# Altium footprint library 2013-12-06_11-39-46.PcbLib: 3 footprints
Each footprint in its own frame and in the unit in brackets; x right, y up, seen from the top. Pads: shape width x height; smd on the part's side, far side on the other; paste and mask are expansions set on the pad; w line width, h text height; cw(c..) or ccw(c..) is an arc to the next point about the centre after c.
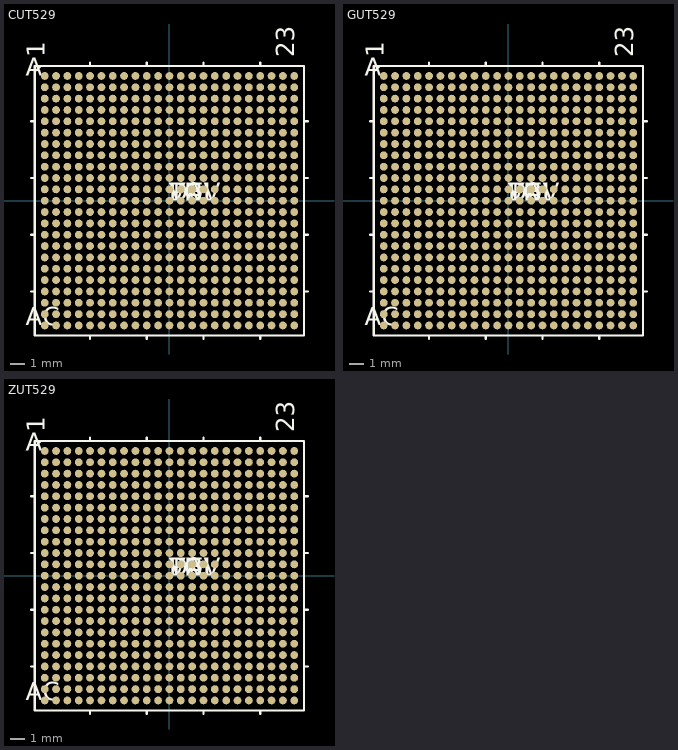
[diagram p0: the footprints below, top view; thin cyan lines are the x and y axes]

## CUT529 [mm]
pads (529):
  round 0.55 smd: A1(-8.8,8.8) A2(-8,8.8) A3(-7.2,8.8) A4(-6.4,8.8) A5(-5.6,8.8) A6(-4.8,8.8) A7(-4,8.8) A8(-3.2,8.8) A9(-2.4,8.8) A10(-1.6,8.8) A11(-0.8,8.8) A12(0,8.8) A13(0.8,8.8) A14(1.6,8.8) A15(2.4,8.8) A16(3.2,8.8) A17(4,8.8) A18(4.8,8.8) A19(5.6,8.8) A20(6.4,8.8) A21(7.2,8.8) A22(8,8.8) A23(8.8,8.8) AA1(-8.8,-7.2) AA2(-8,-7.2) AA3(-7.2,-7.2) AA4(-6.4,-7.2) AA5(-5.6,-7.2) AA6(-4.8,-7.2) AA7(-4,-7.2) AA8(-3.2,-7.2) AA9(-2.4,-7.2) AA10(-1.6,-7.2) AA11(-0.8,-7.2) AA12(0,-7.2) AA13(0.8,-7.2) AA14(1.6,-7.2) AA15(2.4,-7.2) AA16(3.2,-7.2) AA17(4,-7.2) AA18(4.8,-7.2) AA19(5.6,-7.2) AA20(6.4,-7.2) AA21(7.2,-7.2) AA22(8,-7.2) AA23(8.8,-7.2) AB1(-8.8,-8) AB2(-8,-8) AB3(-7.2,-8) AB4(-6.4,-8) AB5(-5.6,-8) AB6(-4.8,-8) AB7(-4,-8) AB8(-3.2,-8) AB9(-2.4,-8) AB10(-1.6,-8) AB11(-0.8,-8) AB12(0,-8) AB13(0.8,-8) AB14(1.6,-8) AB15(2.4,-8) AB16(3.2,-8) AB17(4,-8) AB18(4.8,-8) AB19(5.6,-8) AB20(6.4,-8) AB21(7.2,-8) AB22(8,-8) AB23(8.8,-8) AC1(-8.8,-8.8) AC2(-8,-8.8) AC3(-7.2,-8.8) AC4(-6.4,-8.8) AC5(-5.6,-8.8) AC6(-4.8,-8.8) AC7(-4,-8.8) AC8(-3.2,-8.8) AC9(-2.4,-8.8) AC10(-1.6,-8.8) AC11(-0.8,-8.8) AC12(0,-8.8) AC13(0.8,-8.8) AC14(1.6,-8.8) AC15(2.4,-8.8) AC16(3.2,-8.8) AC17(4,-8.8) AC18(4.8,-8.8) AC19(5.6,-8.8) AC20(6.4,-8.8) AC21(7.2,-8.8) AC22(8,-8.8) AC23(8.8,-8.8) B1(-8.8,8) B2(-8,8) B3(-7.2,8) B4(-6.4,8) B5(-5.6,8) B6(-4.8,8) B7(-4,8) B8(-3.2,8) B9(-2.4,8) B10(-1.6,8) B11(-0.8,8) B12(0,8) B13(0.8,8) B14(1.6,8) B15(2.4,8) B16(3.2,8) B17(4,8) B18(4.8,8) B19(5.6,8) B20(6.4,8) B21(7.2,8) B22(8,8) B23(8.8,8) C1(-8.8,7.2) C2(-8,7.2) C3(-7.2,7.2) C4(-6.4,7.2) C5(-5.6,7.2) C6(-4.8,7.2) C7(-4,7.2) C8(-3.2,7.2) C9(-2.4,7.2) C10(-1.6,7.2) C11(-0.8,7.2) C12(0,7.2) C13(0.8,7.2) C14(1.6,7.2) C15(2.4,7.2) C16(3.2,7.2) C17(4,7.2) C18(4.8,7.2) C19(5.6,7.2) C20(6.4,7.2) C21(7.2,7.2) C22(8,7.2) C23(8.8,7.2) D1(-8.8,6.4) D2(-8,6.4) D3(-7.2,6.4) D4(-6.4,6.4) D5(-5.6,6.4) D6(-4.8,6.4) D7(-4,6.4) D8(-3.2,6.4) D9(-2.4,6.4) D10(-1.6,6.4) D11(-0.8,6.4) D12(0,6.4) D13(0.8,6.4) D14(1.6,6.4) D15(2.4,6.4) D16(3.2,6.4) D17(4,6.4) D18(4.8,6.4) D19(5.6,6.4) D20(6.4,6.4) D21(7.2,6.4) D22(8,6.4) D23(8.8,6.4) E1(-8.8,5.6) E2(-8,5.6) E3(-7.2,5.6) E4(-6.4,5.6) E5(-5.6,5.6) E6(-4.8,5.6) E7(-4,5.6) E8(-3.2,5.6) E9(-2.4,5.6) E10(-1.6,5.6) E11(-0.8,5.6) E12(0,5.6) E13(0.8,5.6) E14(1.6,5.6) E15(2.4,5.6) E16(3.2,5.6) E17(4,5.6) E18(4.8,5.6) E19(5.6,5.6) E20(6.4,5.6) E21(7.2,5.6) E22(8,5.6) E23(8.8,5.6) F1(-8.8,4.8) F2(-8,4.8) F3(-7.2,4.8) F4(-6.4,4.8) F5(-5.6,4.8) F6(-4.8,4.8) F7(-4,4.8) F8(-3.2,4.8) F9(-2.4,4.8) F10(-1.6,4.8) F11(-0.8,4.8) F12(0,4.8) F13(0.8,4.8) F14(1.6,4.8) F15(2.4,4.8) F16(3.2,4.8) F17(4,4.8) F18(4.8,4.8) F19(5.6,4.8) F20(6.4,4.8) F21(7.2,4.8) F22(8,4.8) F23(8.8,4.8) G1(-8.8,4) G2(-8,4) G3(-7.2,4) G4(-6.4,4) G5(-5.6,4) G6(-4.8,4) G7(-4,4) G8(-3.2,4) G9(-2.4,4) G10(-1.6,4) G11(-0.8,4) G12(0,4) G13(0.8,4) G14(1.6,4) G15(2.4,4) G16(3.2,4) G17(4,4) G18(4.8,4) G19(5.6,4) G20(6.4,4) G21(7.2,4) G22(8,4) G23(8.8,4) H1(-8.8,3.2) H2(-8,3.2) H3(-7.2,3.2) H4(-6.4,3.2) H5(-5.6,3.2) H6(-4.8,3.2) H7(-4,3.2) H8(-3.2,3.2) H9(-2.4,3.2) H10(-1.6,3.2) H11(-0.8,3.2) H12(0,3.2) H13(0.8,3.2) H14(1.6,3.2) H15(2.4,3.2) H16(3.2,3.2) H17(4,3.2) H18(4.8,3.2) H19(5.6,3.2) H20(6.4,3.2) H21(7.2,3.2) H22(8,3.2) H23(8.8,3.2) J1(-8.8,2.4) J2(-8,2.4) J3(-7.2,2.4) J4(-6.4,2.4) J5(-5.6,2.4) J6(-4.8,2.4) J7(-4,2.4) J8(-3.2,2.4) J9(-2.4,2.4) J10(-1.6,2.4) J11(-0.8,2.4) J12(0,2.4) J13(0.8,2.4) J14(1.6,2.4) J15(2.4,2.4) J16(3.2,2.4) J17(4,2.4) J18(4.8,2.4) J19(5.6,2.4) J20(6.4,2.4) J21(7.2,2.4) J22(8,2.4) J23(8.8,2.4) K1(-8.8,1.6) K2(-8,1.6) K3(-7.2,1.6) K4(-6.4,1.6) K5(-5.6,1.6) K6(-4.8,1.6) K7(-4,1.6) K8(-3.2,1.6) K9(-2.4,1.6) K10(-1.6,1.6) K11(-0.8,1.6) K12(0,1.6) K13(0.8,1.6) K14(1.6,1.6) K15(2.4,1.6) K16(3.2,1.6) K17(4,1.6) K18(4.8,1.6) K19(5.6,1.6) K20(6.4,1.6) K21(7.2,1.6) K22(8,1.6) K23(8.8,1.6) L1(-8.8,0.8) L2(-8,0.8) L3(-7.2,0.8) L4(-6.4,0.8) L5(-5.6,0.8) L6(-4.8,0.8) L7(-4,0.8) L8(-3.2,0.8) L9(-2.4,0.8) L10(-1.6,0.8) L11(-0.8,0.8) L12(0,0.8) L13(0.8,0.8) L14(1.6,0.8) L15(2.4,0.8) L16(3.2,0.8) L17(4,0.8) L18(4.8,0.8) L19(5.6,0.8) L20(6.4,0.8) L21(7.2,0.8) L22(8,0.8) L23(8.8,0.8) M1(-8.8,0) M2(-8,0) M3(-7.2,0) M4(-6.4,0) M5(-5.6,0) M6(-4.8,0) M7(-4,0) M8(-3.2,0) M9(-2.4,0) M10(-1.6,0) M11(-0.8,0) M12(0,0) M13(0.8,0) M14(1.6,0) M15(2.4,0) M16(3.2,0) M17(4,0) M18(4.8,0) M19(5.6,0) M20(6.4,0) M21(7.2,0) M22(8,0) M23(8.8,0) N1(-8.8,-0.8) N2(-8,-0.8) N3(-7.2,-0.8) N4(-6.4,-0.8) N5(-5.6,-0.8) N6(-4.8,-0.8) N7(-4,-0.8) N8(-3.2,-0.8) N9(-2.4,-0.8) N10(-1.6,-0.8) N11(-0.8,-0.8) N12(0,-0.8) N13(0.8,-0.8) N14(1.6,-0.8) N15(2.4,-0.8) N16(3.2,-0.8) N17(4,-0.8) N18(4.8,-0.8) N19(5.6,-0.8) N20(6.4,-0.8) N21(7.2,-0.8) N22(8,-0.8) N23(8.8,-0.8) P1(-8.8,-1.6) P2(-8,-1.6) P3(-7.2,-1.6) P4(-6.4,-1.6) P5(-5.6,-1.6) P6(-4.8,-1.6) P7(-4,-1.6) P8(-3.2,-1.6) P9(-2.4,-1.6) P10(-1.6,-1.6) P11(-0.8,-1.6) P12(0,-1.6) P13(0.8,-1.6) P14(1.6,-1.6) P15(2.4,-1.6) P16(3.2,-1.6) P17(4,-1.6) P18(4.8,-1.6) P19(5.6,-1.6) P20(6.4,-1.6) P21(7.2,-1.6) P22(8,-1.6) P23(8.8,-1.6) R1(-8.8,-2.4) R2(-8,-2.4) R3(-7.2,-2.4) R4(-6.4,-2.4) R5(-5.6,-2.4) R6(-4.8,-2.4) R7(-4,-2.4) R8(-3.2,-2.4) R9(-2.4,-2.4) R10(-1.6,-2.4) R11(-0.8,-2.4) R12(0,-2.4) R13(0.8,-2.4) R14(1.6,-2.4) R15(2.4,-2.4) R16(3.2,-2.4) R17(4,-2.4) R18(4.8,-2.4) R19(5.6,-2.4) R20(6.4,-2.4) R21(7.2,-2.4) R22(8,-2.4) R23(8.8,-2.4) T1(-8.8,-3.2) T2(-8,-3.2) T3(-7.2,-3.2) T4(-6.4,-3.2) T5(-5.6,-3.2) T6(-4.8,-3.2) T7(-4,-3.2) T8(-3.2,-3.2) T9(-2.4,-3.2) T10(-1.6,-3.2) T11(-0.8,-3.2) T12(0,-3.2) T13(0.8,-3.2) T14(1.6,-3.2) T15(2.4,-3.2) T16(3.2,-3.2) T17(4,-3.2) T18(4.8,-3.2) T19(5.6,-3.2) T20(6.4,-3.2) T21(7.2,-3.2) T22(8,-3.2) T23(8.8,-3.2) U1(-8.8,-4) U2(-8,-4) U3(-7.2,-4) U4(-6.4,-4) U5(-5.6,-4) U6(-4.8,-4) U7(-4,-4) U8(-3.2,-4) U9(-2.4,-4) U10(-1.6,-4) U11(-0.8,-4) U12(0,-4) U13(0.8,-4) U14(1.6,-4) U15(2.4,-4) U16(3.2,-4) U17(4,-4) U18(4.8,-4) U19(5.6,-4) U20(6.4,-4) U21(7.2,-4) U22(8,-4) U23(8.8,-4) V1(-8.8,-4.8) V2(-8,-4.8) V3(-7.2,-4.8) V4(-6.4,-4.8) V5(-5.6,-4.8) V6(-4.8,-4.8) V7(-4,-4.8) V8(-3.2,-4.8) V9(-2.4,-4.8) V10(-1.6,-4.8) V11(-0.8,-4.8) V12(0,-4.8) V13(0.8,-4.8) V14(1.6,-4.8) V15(2.4,-4.8) V16(3.2,-4.8) V17(4,-4.8) V18(4.8,-4.8) V19(5.6,-4.8) V20(6.4,-4.8) V21(7.2,-4.8) V22(8,-4.8) V23(8.8,-4.8) W1(-8.8,-5.6) W2(-8,-5.6) W3(-7.2,-5.6) W4(-6.4,-5.6) W5(-5.6,-5.6) W6(-4.8,-5.6) W7(-4,-5.6) W8(-3.2,-5.6) W9(-2.4,-5.6) W10(-1.6,-5.6) W11(-0.8,-5.6) W12(0,-5.6) W13(0.8,-5.6) W14(1.6,-5.6) W15(2.4,-5.6) W16(3.2,-5.6) W17(4,-5.6) W18(4.8,-5.6) W19(5.6,-5.6) W20(6.4,-5.6) W21(7.2,-5.6) W22(8,-5.6) W23(8.8,-5.6) Y1(-8.8,-6.4) Y2(-8,-6.4) Y3(-7.2,-6.4) Y4(-6.4,-6.4) Y5(-5.6,-6.4) Y6(-4.8,-6.4) Y7(-4,-6.4) Y8(-3.2,-6.4) Y9(-2.4,-6.4) Y10(-1.6,-6.4) Y11(-0.8,-6.4) Y12(0,-6.4) Y13(0.8,-6.4) Y14(1.6,-6.4) Y15(2.4,-6.4) Y16(3.2,-6.4) Y17(4,-6.4) Y18(4.8,-6.4) Y19(5.6,-6.4) Y20(6.4,-6.4) Y21(7.2,-6.4) Y22(8,-6.4) Y23(8.8,-6.4)
Top Overlay:
  lines w0.152: -9.754,-6.4 -9.5,-6.4 ; -9.754,-2.4 -9.5,-2.4 ; -9.754,1.6 -9.5,1.6 ; -9.754,5.6 -9.5,5.6 ; -9.5,9.1 -9.1,9.5 ; -5.6,-9.754 -5.6,-9.5 ; -5.6,9.5 -5.6,9.754 ; -1.6,-9.754 -1.6,-9.5 ; -1.6,9.5 -1.6,9.754 ; 2.4,-9.754 2.4,-9.5 ; 2.4,9.5 2.4,9.754 ; 6.4,-9.754 6.4,-9.5 ; 6.4,9.5 6.4,9.754 ; 9.5,-6.4 9.754,-6.4 ; 9.5,-2.4 9.754,-2.4 ; 9.5,1.6 9.754,1.6 ; 9.5,5.6 9.754,5.6 ; -9.5,-9.5 9.5,-9.5 9.5,9.5 -9.5,9.5 -9.5,-9.5
  text "A" at -10.135,8.8 h1.27
  text "AC" at -10.135,-8.8 h1.27
  text "1" at -8.8,10.135 h1.27
  text "23" at 8.8,10.135 h1.27
  text "PN" at 0,0 h1.27
  text "DEV" at 0,0 h1.27
  text "VAL" at 0,0 h1.27
  text "TOL" at 0,0 h1.27
Bottom Overlay:
  text "A" at -10.135,8.8 h1.27
  text "AC" at -10.135,-8.8 h1.27
  text "1" at -8.8,10.135 h1.27
  text "23" at 8.8,10.135 h1.27
Mechanical 1:
  lines w0: -9.5,9.1 -9.1,9.5 ; -9.5,-9.5 9.5,-9.5 9.5,9.5 -9.5,9.5 -9.5,-9.5
  text "A" at -10.135,8.8 h1.27
  text "AC" at -10.135,-8.8 h1.27
  text "1" at -8.8,10.135 h1.27
  text "23" at 8.8,10.135 h1.27
  text "RefDes2" at 0,0 h1.27

## GUT529 [mm]
pads (529):
  round 0.55 smd: A1(-8.8,8.8) A2(-8,8.8) A3(-7.2,8.8) A4(-6.4,8.8) A5(-5.6,8.8) A6(-4.8,8.8) A7(-4,8.8) A8(-3.2,8.8) A9(-2.4,8.8) A10(-1.6,8.8) A11(-0.8,8.8) A12(0,8.8) A13(0.8,8.8) A14(1.6,8.8) A15(2.4,8.8) A16(3.2,8.8) A17(4,8.8) A18(4.8,8.8) A19(5.6,8.8) A20(6.4,8.8) A21(7.2,8.8) A22(8,8.8) A23(8.8,8.8) AA1(-8.8,-7.2) AA2(-8,-7.2) AA3(-7.2,-7.2) AA4(-6.4,-7.2) AA5(-5.6,-7.2) AA6(-4.8,-7.2) AA7(-4,-7.2) AA8(-3.2,-7.2) AA9(-2.4,-7.2) AA10(-1.6,-7.2) AA11(-0.8,-7.2) AA12(0,-7.2) AA13(0.8,-7.2) AA14(1.6,-7.2) AA15(2.4,-7.2) AA16(3.2,-7.2) AA17(4,-7.2) AA18(4.8,-7.2) AA19(5.6,-7.2) AA20(6.4,-7.2) AA21(7.2,-7.2) AA22(8,-7.2) AA23(8.8,-7.2) AB1(-8.8,-8) AB2(-8,-8) AB3(-7.2,-8) AB4(-6.4,-8) AB5(-5.6,-8) AB6(-4.8,-8) AB7(-4,-8) AB8(-3.2,-8) AB9(-2.4,-8) AB10(-1.6,-8) AB11(-0.8,-8) AB12(0,-8) AB13(0.8,-8) AB14(1.6,-8) AB15(2.4,-8) AB16(3.2,-8) AB17(4,-8) AB18(4.8,-8) AB19(5.6,-8) AB20(6.4,-8) AB21(7.2,-8) AB22(8,-8) AB23(8.8,-8) AC1(-8.8,-8.8) AC2(-8,-8.8) AC3(-7.2,-8.8) AC4(-6.4,-8.8) AC5(-5.6,-8.8) AC6(-4.8,-8.8) AC7(-4,-8.8) AC8(-3.2,-8.8) AC9(-2.4,-8.8) AC10(-1.6,-8.8) AC11(-0.8,-8.8) AC12(0,-8.8) AC13(0.8,-8.8) AC14(1.6,-8.8) AC15(2.4,-8.8) AC16(3.2,-8.8) AC17(4,-8.8) AC18(4.8,-8.8) AC19(5.6,-8.8) AC20(6.4,-8.8) AC21(7.2,-8.8) AC22(8,-8.8) AC23(8.8,-8.8) B1(-8.8,8) B2(-8,8) B3(-7.2,8) B4(-6.4,8) B5(-5.6,8) B6(-4.8,8) B7(-4,8) B8(-3.2,8) B9(-2.4,8) B10(-1.6,8) B11(-0.8,8) B12(0,8) B13(0.8,8) B14(1.6,8) B15(2.4,8) B16(3.2,8) B17(4,8) B18(4.8,8) B19(5.6,8) B20(6.4,8) B21(7.2,8) B22(8,8) B23(8.8,8) C1(-8.8,7.2) C2(-8,7.2) C3(-7.2,7.2) C4(-6.4,7.2) C5(-5.6,7.2) C6(-4.8,7.2) C7(-4,7.2) C8(-3.2,7.2) C9(-2.4,7.2) C10(-1.6,7.2) C11(-0.8,7.2) C12(0,7.2) C13(0.8,7.2) C14(1.6,7.2) C15(2.4,7.2) C16(3.2,7.2) C17(4,7.2) C18(4.8,7.2) C19(5.6,7.2) C20(6.4,7.2) C21(7.2,7.2) C22(8,7.2) C23(8.8,7.2) D1(-8.8,6.4) D2(-8,6.4) D3(-7.2,6.4) D4(-6.4,6.4) D5(-5.6,6.4) D6(-4.8,6.4) D7(-4,6.4) D8(-3.2,6.4) D9(-2.4,6.4) D10(-1.6,6.4) D11(-0.8,6.4) D12(0,6.4) D13(0.8,6.4) D14(1.6,6.4) D15(2.4,6.4) D16(3.2,6.4) D17(4,6.4) D18(4.8,6.4) D19(5.6,6.4) D20(6.4,6.4) D21(7.2,6.4) D22(8,6.4) D23(8.8,6.4) E1(-8.8,5.6) E2(-8,5.6) E3(-7.2,5.6) E4(-6.4,5.6) E5(-5.6,5.6) E6(-4.8,5.6) E7(-4,5.6) E8(-3.2,5.6) E9(-2.4,5.6) E10(-1.6,5.6) E11(-0.8,5.6) E12(0,5.6) E13(0.8,5.6) E14(1.6,5.6) E15(2.4,5.6) E16(3.2,5.6) E17(4,5.6) E18(4.8,5.6) E19(5.6,5.6) E20(6.4,5.6) E21(7.2,5.6) E22(8,5.6) E23(8.8,5.6) F1(-8.8,4.8) F2(-8,4.8) F3(-7.2,4.8) F4(-6.4,4.8) F5(-5.6,4.8) F6(-4.8,4.8) F7(-4,4.8) F8(-3.2,4.8) F9(-2.4,4.8) F10(-1.6,4.8) F11(-0.8,4.8) F12(0,4.8) F13(0.8,4.8) F14(1.6,4.8) F15(2.4,4.8) F16(3.2,4.8) F17(4,4.8) F18(4.8,4.8) F19(5.6,4.8) F20(6.4,4.8) F21(7.2,4.8) F22(8,4.8) F23(8.8,4.8) G1(-8.8,4) G2(-8,4) G3(-7.2,4) G4(-6.4,4) G5(-5.6,4) G6(-4.8,4) G7(-4,4) G8(-3.2,4) G9(-2.4,4) G10(-1.6,4) G11(-0.8,4) G12(0,4) G13(0.8,4) G14(1.6,4) G15(2.4,4) G16(3.2,4) G17(4,4) G18(4.8,4) G19(5.6,4) G20(6.4,4) G21(7.2,4) G22(8,4) G23(8.8,4) H1(-8.8,3.2) H2(-8,3.2) H3(-7.2,3.2) H4(-6.4,3.2) H5(-5.6,3.2) H6(-4.8,3.2) H7(-4,3.2) H8(-3.2,3.2) H9(-2.4,3.2) H10(-1.6,3.2) H11(-0.8,3.2) H12(0,3.2) H13(0.8,3.2) H14(1.6,3.2) H15(2.4,3.2) H16(3.2,3.2) H17(4,3.2) H18(4.8,3.2) H19(5.6,3.2) H20(6.4,3.2) H21(7.2,3.2) H22(8,3.2) H23(8.8,3.2) J1(-8.8,2.4) J2(-8,2.4) J3(-7.2,2.4) J4(-6.4,2.4) J5(-5.6,2.4) J6(-4.8,2.4) J7(-4,2.4) J8(-3.2,2.4) J9(-2.4,2.4) J10(-1.6,2.4) J11(-0.8,2.4) J12(0,2.4) J13(0.8,2.4) J14(1.6,2.4) J15(2.4,2.4) J16(3.2,2.4) J17(4,2.4) J18(4.8,2.4) J19(5.6,2.4) J20(6.4,2.4) J21(7.2,2.4) J22(8,2.4) J23(8.8,2.4) K1(-8.8,1.6) K2(-8,1.6) K3(-7.2,1.6) K4(-6.4,1.6) K5(-5.6,1.6) K6(-4.8,1.6) K7(-4,1.6) K8(-3.2,1.6) K9(-2.4,1.6) K10(-1.6,1.6) K11(-0.8,1.6) K12(0,1.6) K13(0.8,1.6) K14(1.6,1.6) K15(2.4,1.6) K16(3.2,1.6) K17(4,1.6) K18(4.8,1.6) K19(5.6,1.6) K20(6.4,1.6) K21(7.2,1.6) K22(8,1.6) K23(8.8,1.6) L1(-8.8,0.8) L2(-8,0.8) L3(-7.2,0.8) L4(-6.4,0.8) L5(-5.6,0.8) L6(-4.8,0.8) L7(-4,0.8) L8(-3.2,0.8) L9(-2.4,0.8) L10(-1.6,0.8) L11(-0.8,0.8) L12(0,0.8) L13(0.8,0.8) L14(1.6,0.8) L15(2.4,0.8) L16(3.2,0.8) L17(4,0.8) L18(4.8,0.8) L19(5.6,0.8) L20(6.4,0.8) L21(7.2,0.8) L22(8,0.8) L23(8.8,0.8) M1(-8.8,0) M2(-8,0) M3(-7.2,0) M4(-6.4,0) M5(-5.6,0) M6(-4.8,0) M7(-4,0) M8(-3.2,0) M9(-2.4,0) M10(-1.6,0) M11(-0.8,0) M12(0,0) M13(0.8,0) M14(1.6,0) M15(2.4,0) M16(3.2,0) M17(4,0) M18(4.8,0) M19(5.6,0) M20(6.4,0) M21(7.2,0) M22(8,0) M23(8.8,0) N1(-8.8,-0.8) N2(-8,-0.8) N3(-7.2,-0.8) N4(-6.4,-0.8) N5(-5.6,-0.8) N6(-4.8,-0.8) N7(-4,-0.8) N8(-3.2,-0.8) N9(-2.4,-0.8) N10(-1.6,-0.8) N11(-0.8,-0.8) N12(0,-0.8) N13(0.8,-0.8) N14(1.6,-0.8) N15(2.4,-0.8) N16(3.2,-0.8) N17(4,-0.8) N18(4.8,-0.8) N19(5.6,-0.8) N20(6.4,-0.8) N21(7.2,-0.8) N22(8,-0.8) N23(8.8,-0.8) P1(-8.8,-1.6) P2(-8,-1.6) P3(-7.2,-1.6) P4(-6.4,-1.6) P5(-5.6,-1.6) P6(-4.8,-1.6) P7(-4,-1.6) P8(-3.2,-1.6) P9(-2.4,-1.6) P10(-1.6,-1.6) P11(-0.8,-1.6) P12(0,-1.6) P13(0.8,-1.6) P14(1.6,-1.6) P15(2.4,-1.6) P16(3.2,-1.6) P17(4,-1.6) P18(4.8,-1.6) P19(5.6,-1.6) P20(6.4,-1.6) P21(7.2,-1.6) P22(8,-1.6) P23(8.8,-1.6) R1(-8.8,-2.4) R2(-8,-2.4) R3(-7.2,-2.4) R4(-6.4,-2.4) R5(-5.6,-2.4) R6(-4.8,-2.4) R7(-4,-2.4) R8(-3.2,-2.4) R9(-2.4,-2.4) R10(-1.6,-2.4) R11(-0.8,-2.4) R12(0,-2.4) R13(0.8,-2.4) R14(1.6,-2.4) R15(2.4,-2.4) R16(3.2,-2.4) R17(4,-2.4) R18(4.8,-2.4) R19(5.6,-2.4) R20(6.4,-2.4) R21(7.2,-2.4) R22(8,-2.4) R23(8.8,-2.4) T1(-8.8,-3.2) T2(-8,-3.2) T3(-7.2,-3.2) T4(-6.4,-3.2) T5(-5.6,-3.2) T6(-4.8,-3.2) T7(-4,-3.2) T8(-3.2,-3.2) T9(-2.4,-3.2) T10(-1.6,-3.2) T11(-0.8,-3.2) T12(0,-3.2) T13(0.8,-3.2) T14(1.6,-3.2) T15(2.4,-3.2) T16(3.2,-3.2) T17(4,-3.2) T18(4.8,-3.2) T19(5.6,-3.2) T20(6.4,-3.2) T21(7.2,-3.2) T22(8,-3.2) T23(8.8,-3.2) U1(-8.8,-4) U2(-8,-4) U3(-7.2,-4) U4(-6.4,-4) U5(-5.6,-4) U6(-4.8,-4) U7(-4,-4) U8(-3.2,-4) U9(-2.4,-4) U10(-1.6,-4) U11(-0.8,-4) U12(0,-4) U13(0.8,-4) U14(1.6,-4) U15(2.4,-4) U16(3.2,-4) U17(4,-4) U18(4.8,-4) U19(5.6,-4) U20(6.4,-4) U21(7.2,-4) U22(8,-4) U23(8.8,-4) V1(-8.8,-4.8) V2(-8,-4.8) V3(-7.2,-4.8) V4(-6.4,-4.8) V5(-5.6,-4.8) V6(-4.8,-4.8) V7(-4,-4.8) V8(-3.2,-4.8) V9(-2.4,-4.8) V10(-1.6,-4.8) V11(-0.8,-4.8) V12(0,-4.8) V13(0.8,-4.8) V14(1.6,-4.8) V15(2.4,-4.8) V16(3.2,-4.8) V17(4,-4.8) V18(4.8,-4.8) V19(5.6,-4.8) V20(6.4,-4.8) V21(7.2,-4.8) V22(8,-4.8) V23(8.8,-4.8) W1(-8.8,-5.6) W2(-8,-5.6) W3(-7.2,-5.6) W4(-6.4,-5.6) W5(-5.6,-5.6) W6(-4.8,-5.6) W7(-4,-5.6) W8(-3.2,-5.6) W9(-2.4,-5.6) W10(-1.6,-5.6) W11(-0.8,-5.6) W12(0,-5.6) W13(0.8,-5.6) W14(1.6,-5.6) W15(2.4,-5.6) W16(3.2,-5.6) W17(4,-5.6) W18(4.8,-5.6) W19(5.6,-5.6) W20(6.4,-5.6) W21(7.2,-5.6) W22(8,-5.6) W23(8.8,-5.6) Y1(-8.8,-6.4) Y2(-8,-6.4) Y3(-7.2,-6.4) Y4(-6.4,-6.4) Y5(-5.6,-6.4) Y6(-4.8,-6.4) Y7(-4,-6.4) Y8(-3.2,-6.4) Y9(-2.4,-6.4) Y10(-1.6,-6.4) Y11(-0.8,-6.4) Y12(0,-6.4) Y13(0.8,-6.4) Y14(1.6,-6.4) Y15(2.4,-6.4) Y16(3.2,-6.4) Y17(4,-6.4) Y18(4.8,-6.4) Y19(5.6,-6.4) Y20(6.4,-6.4) Y21(7.2,-6.4) Y22(8,-6.4) Y23(8.8,-6.4)
Top Overlay:
  lines w0.152: -9.754,-6.4 -9.5,-6.4 ; -9.754,-2.4 -9.5,-2.4 ; -9.754,1.6 -9.5,1.6 ; -9.754,5.6 -9.5,5.6 ; -9.5,9.1 -9.1,9.5 ; -5.6,-9.754 -5.6,-9.5 ; -5.6,9.5 -5.6,9.754 ; -1.6,-9.754 -1.6,-9.5 ; -1.6,9.5 -1.6,9.754 ; 2.4,-9.754 2.4,-9.5 ; 2.4,9.5 2.4,9.754 ; 6.4,-9.754 6.4,-9.5 ; 6.4,9.5 6.4,9.754 ; 9.5,-6.4 9.754,-6.4 ; 9.5,-2.4 9.754,-2.4 ; 9.5,1.6 9.754,1.6 ; 9.5,5.6 9.754,5.6 ; -9.5,-9.5 9.5,-9.5 9.5,9.5 -9.5,9.5 -9.5,-9.5
  text "A" at -10.135,8.8 h1.27
  text "AC" at -10.135,-8.8 h1.27
  text "1" at -8.8,10.135 h1.27
  text "23" at 8.8,10.135 h1.27
  text "PN" at 0,0 h1.27
  text "DEV" at 0,0 h1.27
  text "VAL" at 0,0 h1.27
  text "TOL" at 0,0 h1.27
Bottom Overlay:
  text "A" at -10.135,8.8 h1.27
  text "AC" at -10.135,-8.8 h1.27
  text "1" at -8.8,10.135 h1.27
  text "23" at 8.8,10.135 h1.27
Mechanical 1:
  lines w0: -9.5,9.1 -9.1,9.5 ; -9.5,-9.5 9.5,-9.5 9.5,9.5 -9.5,9.5 -9.5,-9.5
  text "A" at -10.135,8.8 h1.27
  text "AC" at -10.135,-8.8 h1.27
  text "1" at -8.8,10.135 h1.27
  text "23" at 8.8,10.135 h1.27
  text "RefDes2" at 0,0 h1.27

## ZUT529 [mm]
pads (529):
  round 0.55 smd: A1(-8.8,8.8) A2(-8,8.8) A3(-7.2,8.8) A4(-6.4,8.8) A5(-5.6,8.8) A6(-4.8,8.8) A7(-4,8.8) A8(-3.2,8.8) A9(-2.4,8.8) A10(-1.6,8.8) A11(-0.8,8.8) A12(0,8.8) A13(0.8,8.8) A14(1.6,8.8) A15(2.4,8.8) A16(3.2,8.8) A17(4,8.8) A18(4.8,8.8) A19(5.6,8.8) A20(6.4,8.8) A21(7.2,8.8) A22(8,8.8) A23(8.8,8.8) AA1(-8.8,-7.2) AA2(-8,-7.2) AA3(-7.2,-7.2) AA4(-6.4,-7.2) AA5(-5.6,-7.2) AA6(-4.8,-7.2) AA7(-4,-7.2) AA8(-3.2,-7.2) AA9(-2.4,-7.2) AA10(-1.6,-7.2) AA11(-0.8,-7.2) AA12(0,-7.2) AA13(0.8,-7.2) AA14(1.6,-7.2) AA15(2.4,-7.2) AA16(3.2,-7.2) AA17(4,-7.2) AA18(4.8,-7.2) AA19(5.6,-7.2) AA20(6.4,-7.2) AA21(7.2,-7.2) AA22(8,-7.2) AA23(8.8,-7.2) AB1(-8.8,-8) AB2(-8,-8) AB3(-7.2,-8) AB4(-6.4,-8) AB5(-5.6,-8) AB6(-4.8,-8) AB7(-4,-8) AB8(-3.2,-8) AB9(-2.4,-8) AB10(-1.6,-8) AB11(-0.8,-8) AB12(0,-8) AB13(0.8,-8) AB14(1.6,-8) AB15(2.4,-8) AB16(3.2,-8) AB17(4,-8) AB18(4.8,-8) AB19(5.6,-8) AB20(6.4,-8) AB21(7.2,-8) AB22(8,-8) AB23(8.8,-8) AC1(-8.8,-8.8) AC2(-8,-8.8) AC3(-7.2,-8.8) AC4(-6.4,-8.8) AC5(-5.6,-8.8) AC6(-4.8,-8.8) AC7(-4,-8.8) AC8(-3.2,-8.8) AC9(-2.4,-8.8) AC10(-1.6,-8.8) AC11(-0.8,-8.8) AC12(0,-8.8) AC13(0.8,-8.8) AC14(1.6,-8.8) AC15(2.4,-8.8) AC16(3.2,-8.8) AC17(4,-8.8) AC18(4.8,-8.8) AC19(5.6,-8.8) AC20(6.4,-8.8) AC21(7.2,-8.8) AC22(8,-8.8) AC23(8.8,-8.8) B1(-8.8,8) B2(-8,8) B3(-7.2,8) B4(-6.4,8) B5(-5.6,8) B6(-4.8,8) B7(-4,8) B8(-3.2,8) B9(-2.4,8) B10(-1.6,8) B11(-0.8,8) B12(0,8) B13(0.8,8) B14(1.6,8) B15(2.4,8) B16(3.2,8) B17(4,8) B18(4.8,8) B19(5.6,8) B20(6.4,8) B21(7.2,8) B22(8,8) B23(8.8,8) C1(-8.8,7.2) C2(-8,7.2) C3(-7.2,7.2) C4(-6.4,7.2) C5(-5.6,7.2) C6(-4.8,7.2) C7(-4,7.2) C8(-3.2,7.2) C9(-2.4,7.2) C10(-1.6,7.2) C11(-0.8,7.2) C12(0,7.2) C13(0.8,7.2) C14(1.6,7.2) C15(2.4,7.2) C16(3.2,7.2) C17(4,7.2) C18(4.8,7.2) C19(5.6,7.2) C20(6.4,7.2) C21(7.2,7.2) C22(8,7.2) C23(8.8,7.2) D1(-8.8,6.4) D2(-8,6.4) D3(-7.2,6.4) D4(-6.4,6.4) D5(-5.6,6.4) D6(-4.8,6.4) D7(-4,6.4) D8(-3.2,6.4) D9(-2.4,6.4) D10(-1.6,6.4) D11(-0.8,6.4) D12(0,6.4) D13(0.8,6.4) D14(1.6,6.4) D15(2.4,6.4) D16(3.2,6.4) D17(4,6.4) D18(4.8,6.4) D19(5.6,6.4) D20(6.4,6.4) D21(7.2,6.4) D22(8,6.4) D23(8.8,6.4) E1(-8.8,5.6) E2(-8,5.6) E3(-7.2,5.6) E4(-6.4,5.6) E5(-5.6,5.6) E6(-4.8,5.6) E7(-4,5.6) E8(-3.2,5.6) E9(-2.4,5.6) E10(-1.6,5.6) E11(-0.8,5.6) E12(0,5.6) E13(0.8,5.6) E14(1.6,5.6) E15(2.4,5.6) E16(3.2,5.6) E17(4,5.6) E18(4.8,5.6) E19(5.6,5.6) E20(6.4,5.6) E21(7.2,5.6) E22(8,5.6) E23(8.8,5.6) F1(-8.8,4.8) F2(-8,4.8) F3(-7.2,4.8) F4(-6.4,4.8) F5(-5.6,4.8) F6(-4.8,4.8) F7(-4,4.8) F8(-3.2,4.8) F9(-2.4,4.8) F10(-1.6,4.8) F11(-0.8,4.8) F12(0,4.8) F13(0.8,4.8) F14(1.6,4.8) F15(2.4,4.8) F16(3.2,4.8) F17(4,4.8) F18(4.8,4.8) F19(5.6,4.8) F20(6.4,4.8) F21(7.2,4.8) F22(8,4.8) F23(8.8,4.8) G1(-8.8,4) G2(-8,4) G3(-7.2,4) G4(-6.4,4) G5(-5.6,4) G6(-4.8,4) G7(-4,4) G8(-3.2,4) G9(-2.4,4) G10(-1.6,4) G11(-0.8,4) G12(0,4) G13(0.8,4) G14(1.6,4) G15(2.4,4) G16(3.2,4) G17(4,4) G18(4.8,4) G19(5.6,4) G20(6.4,4) G21(7.2,4) G22(8,4) G23(8.8,4) H1(-8.8,3.2) H2(-8,3.2) H3(-7.2,3.2) H4(-6.4,3.2) H5(-5.6,3.2) H6(-4.8,3.2) H7(-4,3.2) H8(-3.2,3.2) H9(-2.4,3.2) H10(-1.6,3.2) H11(-0.8,3.2) H12(0,3.2) H13(0.8,3.2) H14(1.6,3.2) H15(2.4,3.2) H16(3.2,3.2) H17(4,3.2) H18(4.8,3.2) H19(5.6,3.2) H20(6.4,3.2) H21(7.2,3.2) H22(8,3.2) H23(8.8,3.2) J1(-8.8,2.4) J2(-8,2.4) J3(-7.2,2.4) J4(-6.4,2.4) J5(-5.6,2.4) J6(-4.8,2.4) J7(-4,2.4) J8(-3.2,2.4) J9(-2.4,2.4) J10(-1.6,2.4) J11(-0.8,2.4) J12(0,2.4) J13(0.8,2.4) J14(1.6,2.4) J15(2.4,2.4) J16(3.2,2.4) J17(4,2.4) J18(4.8,2.4) J19(5.6,2.4) J20(6.4,2.4) J21(7.2,2.4) J22(8,2.4) J23(8.8,2.4) K1(-8.8,1.6) K2(-8,1.6) K3(-7.2,1.6) K4(-6.4,1.6) K5(-5.6,1.6) K6(-4.8,1.6) K7(-4,1.6) K8(-3.2,1.6) K9(-2.4,1.6) K10(-1.6,1.6) K11(-0.8,1.6) K12(0,1.6) K13(0.8,1.6) K14(1.6,1.6) K15(2.4,1.6) K16(3.2,1.6) K17(4,1.6) K18(4.8,1.6) K19(5.6,1.6) K20(6.4,1.6) K21(7.2,1.6) K22(8,1.6) K23(8.8,1.6) L1(-8.8,0.8) L2(-8,0.8) L3(-7.2,0.8) L4(-6.4,0.8) L5(-5.6,0.8) L6(-4.8,0.8) L7(-4,0.8) L8(-3.2,0.8) L9(-2.4,0.8) L10(-1.6,0.8) L11(-0.8,0.8) L12(0,0.8) L13(0.8,0.8) L14(1.6,0.8) L15(2.4,0.8) L16(3.2,0.8) L17(4,0.8) L18(4.8,0.8) L19(5.6,0.8) L20(6.4,0.8) L21(7.2,0.8) L22(8,0.8) L23(8.8,0.8) M1(-8.8,0) M2(-8,0) M3(-7.2,0) M4(-6.4,0) M5(-5.6,0) M6(-4.8,0) M7(-4,0) M8(-3.2,0) M9(-2.4,0) M10(-1.6,0) M11(-0.8,0) M12(0,0) M13(0.8,0) M14(1.6,0) M15(2.4,0) M16(3.2,0) M17(4,0) M18(4.8,0) M19(5.6,0) M20(6.4,0) M21(7.2,0) M22(8,0) M23(8.8,0) N1(-8.8,-0.8) N2(-8,-0.8) N3(-7.2,-0.8) N4(-6.4,-0.8) N5(-5.6,-0.8) N6(-4.8,-0.8) N7(-4,-0.8) N8(-3.2,-0.8) N9(-2.4,-0.8) N10(-1.6,-0.8) N11(-0.8,-0.8) N12(0,-0.8) N13(0.8,-0.8) N14(1.6,-0.8) N15(2.4,-0.8) N16(3.2,-0.8) N17(4,-0.8) N18(4.8,-0.8) N19(5.6,-0.8) N20(6.4,-0.8) N21(7.2,-0.8) N22(8,-0.8) N23(8.8,-0.8) P1(-8.8,-1.6) P2(-8,-1.6) P3(-7.2,-1.6) P4(-6.4,-1.6) P5(-5.6,-1.6) P6(-4.8,-1.6) P7(-4,-1.6) P8(-3.2,-1.6) P9(-2.4,-1.6) P10(-1.6,-1.6) P11(-0.8,-1.6) P12(0,-1.6) P13(0.8,-1.6) P14(1.6,-1.6) P15(2.4,-1.6) P16(3.2,-1.6) P17(4,-1.6) P18(4.8,-1.6) P19(5.6,-1.6) P20(6.4,-1.6) P21(7.2,-1.6) P22(8,-1.6) P23(8.8,-1.6) R1(-8.8,-2.4) R2(-8,-2.4) R3(-7.2,-2.4) R4(-6.4,-2.4) R5(-5.6,-2.4) R6(-4.8,-2.4) R7(-4,-2.4) R8(-3.2,-2.4) R9(-2.4,-2.4) R10(-1.6,-2.4) R11(-0.8,-2.4) R12(0,-2.4) R13(0.8,-2.4) R14(1.6,-2.4) R15(2.4,-2.4) R16(3.2,-2.4) R17(4,-2.4) R18(4.8,-2.4) R19(5.6,-2.4) R20(6.4,-2.4) R21(7.2,-2.4) R22(8,-2.4) R23(8.8,-2.4) T1(-8.8,-3.2) T2(-8,-3.2) T3(-7.2,-3.2) T4(-6.4,-3.2) T5(-5.6,-3.2) T6(-4.8,-3.2) T7(-4,-3.2) T8(-3.2,-3.2) T9(-2.4,-3.2) T10(-1.6,-3.2) T11(-0.8,-3.2) T12(0,-3.2) T13(0.8,-3.2) T14(1.6,-3.2) T15(2.4,-3.2) T16(3.2,-3.2) T17(4,-3.2) T18(4.8,-3.2) T19(5.6,-3.2) T20(6.4,-3.2) T21(7.2,-3.2) T22(8,-3.2) T23(8.8,-3.2) U1(-8.8,-4) U2(-8,-4) U3(-7.2,-4) U4(-6.4,-4) U5(-5.6,-4) U6(-4.8,-4) U7(-4,-4) U8(-3.2,-4) U9(-2.4,-4) U10(-1.6,-4) U11(-0.8,-4) U12(0,-4) U13(0.8,-4) U14(1.6,-4) U15(2.4,-4) U16(3.2,-4) U17(4,-4) U18(4.8,-4) U19(5.6,-4) U20(6.4,-4) U21(7.2,-4) U22(8,-4) U23(8.8,-4) V1(-8.8,-4.8) V2(-8,-4.8) V3(-7.2,-4.8) V4(-6.4,-4.8) V5(-5.6,-4.8) V6(-4.8,-4.8) V7(-4,-4.8) V8(-3.2,-4.8) V9(-2.4,-4.8) V10(-1.6,-4.8) V11(-0.8,-4.8) V12(0,-4.8) V13(0.8,-4.8) V14(1.6,-4.8) V15(2.4,-4.8) V16(3.2,-4.8) V17(4,-4.8) V18(4.8,-4.8) V19(5.6,-4.8) V20(6.4,-4.8) V21(7.2,-4.8) V22(8,-4.8) V23(8.8,-4.8) W1(-8.8,-5.6) W2(-8,-5.6) W3(-7.2,-5.6) W4(-6.4,-5.6) W5(-5.6,-5.6) W6(-4.8,-5.6) W7(-4,-5.6) W8(-3.2,-5.6) W9(-2.4,-5.6) W10(-1.6,-5.6) W11(-0.8,-5.6) W12(0,-5.6) W13(0.8,-5.6) W14(1.6,-5.6) W15(2.4,-5.6) W16(3.2,-5.6) W17(4,-5.6) W18(4.8,-5.6) W19(5.6,-5.6) W20(6.4,-5.6) W21(7.2,-5.6) W22(8,-5.6) W23(8.8,-5.6) Y1(-8.8,-6.4) Y2(-8,-6.4) Y3(-7.2,-6.4) Y4(-6.4,-6.4) Y5(-5.6,-6.4) Y6(-4.8,-6.4) Y7(-4,-6.4) Y8(-3.2,-6.4) Y9(-2.4,-6.4) Y10(-1.6,-6.4) Y11(-0.8,-6.4) Y12(0,-6.4) Y13(0.8,-6.4) Y14(1.6,-6.4) Y15(2.4,-6.4) Y16(3.2,-6.4) Y17(4,-6.4) Y18(4.8,-6.4) Y19(5.6,-6.4) Y20(6.4,-6.4) Y21(7.2,-6.4) Y22(8,-6.4) Y23(8.8,-6.4)
Top Overlay:
  lines w0.152: -9.754,-6.4 -9.5,-6.4 ; -9.754,-2.4 -9.5,-2.4 ; -9.754,1.6 -9.5,1.6 ; -9.754,5.6 -9.5,5.6 ; -9.5,9.1 -9.1,9.5 ; -5.6,-9.754 -5.6,-9.5 ; -5.6,9.5 -5.6,9.754 ; -1.6,-9.754 -1.6,-9.5 ; -1.6,9.5 -1.6,9.754 ; 2.4,-9.754 2.4,-9.5 ; 2.4,9.5 2.4,9.754 ; 6.4,-9.754 6.4,-9.5 ; 6.4,9.5 6.4,9.754 ; 9.5,-6.4 9.754,-6.4 ; 9.5,-2.4 9.754,-2.4 ; 9.5,1.6 9.754,1.6 ; 9.5,5.6 9.754,5.6 ; -9.5,-9.5 9.5,-9.5 9.5,9.5 -9.5,9.5 -9.5,-9.5
  text "A" at -10.135,8.8 h1.27
  text "AC" at -10.135,-8.8 h1.27
  text "1" at -8.8,10.135 h1.27
  text "23" at 8.8,10.135 h1.27
  text "PN" at 0,0 h1.27
  text "DEV" at 0,0 h1.27
  text "VAL" at 0,0 h1.27
  text "TOL" at 0,0 h1.27
Bottom Overlay:
  text "A" at -10.135,8.8 h1.27
  text "AC" at -10.135,-8.8 h1.27
  text "1" at -8.8,10.135 h1.27
  text "23" at 8.8,10.135 h1.27
Mechanical 1:
  lines w0: -9.5,9.1 -9.1,9.5 ; -9.5,-9.5 9.5,-9.5 9.5,9.5 -9.5,9.5 -9.5,-9.5
  text "A" at -10.135,8.8 h1.27
  text "AC" at -10.135,-8.8 h1.27
  text "1" at -8.8,10.135 h1.27
  text "23" at 8.8,10.135 h1.27
  text "RefDes2" at 0,0 h1.27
